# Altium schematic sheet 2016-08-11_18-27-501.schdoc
size 331 x 152 mm; SheetNumber: 1; SheetTotal: 1
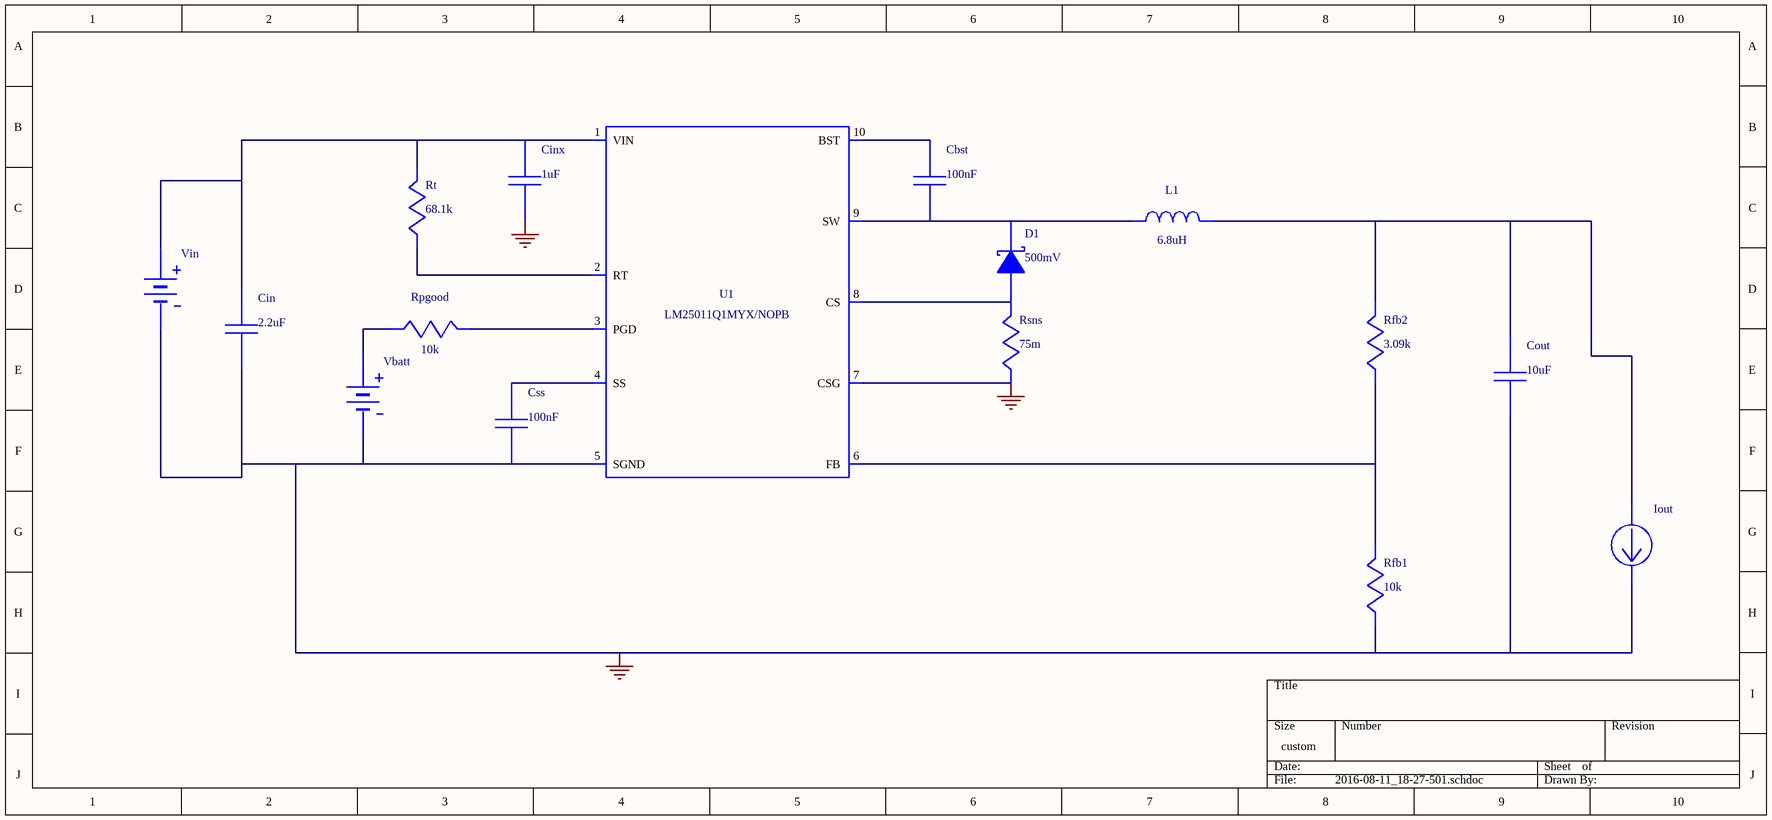
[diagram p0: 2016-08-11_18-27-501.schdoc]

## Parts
Cbst  value 100nF  (hidden comment: GRM21BR71E104KA01L)
Cin  value 2.2uF  (hidden comment: GRM31CR71H225KA88L)
Cinx  value 1uF  (hidden comment: GMK212B7105KG-T)
Cout  value 10uF  (hidden comment: GRM188R60J106ME47D)
Css  value 100nF  (hidden comment: GRM21BR71E104KA01L)
D1  value 500mV  (hidden comment: B240A-13-F)
Iout  WB_CURRENT_LOAD  (value not drawn)
L1  value 6.8uH  (hidden comment: SRN6045-6R8Y)
Rfb1  value 10k  (hidden comment: CRCW040210K0FKED)
Rfb2  value 3.09k  (hidden comment: CRCW04023K09FKED)
Rpgood  value 10k  (hidden comment: CRCW040210K0FKED)
Rsns  value 75m  (hidden comment: CSR1206FK75L0)
Rt  value 68.1k  (hidden comment: CRCW040268K1FKED)
U1  LM25011Q1MYX/NOPB
Vbatt  WB_PRIMITIVE_BATTERY  (value not drawn)
Vin  WB_BATTERY  (value not drawn)

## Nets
0: Cin.2 Cinx.2 Cout.2 Css.2 Iout.2(-) Rfb1.2 Rsns.2 U1.5(SGND) U1.7(CSG) U1.11(DAP) Vbatt.2(-) Vin.2(-)
NetCbst_1: Cbst.1 U1.10(BST)
NetCbst_2: Cbst.2 D1.1(K) L1.1 U1.9(SW)
NetCin_1: Cin.1 Cinx.1 Rt.1 U1.1(VIN) Vin.1(+)
NetCout_1: Cout.1 Iout.1(+) L1.2 Rfb2.1
NetCss_1: Css.1 U1.4(SS)
NetD1_2: D1.2(A) Rsns.1 U1.8(CS)
NetRfb1_1: Rfb1.1 Rfb2.2 U1.6(FB)
NetRpgood_1: Rpgood.1 U1.3(PGD)
NetRpgood_2: Rpgood.2 Vbatt.1(+)
NetRt_2: Rt.2 U1.2(RT)

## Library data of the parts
Cbst Css = GRM21BR71E104KA01L: GRM21BR71E104KA0; Manufacturer Name: MuRata
Cin = GRM31CR71H225KA88L: GRM31CR71H225KA8; Manufacturer Name: MuRata
Cinx = GMK212B7105KG-T: Manufacturer Name: Taiyo Yuden
Cout = GRM188R60J106ME47D: GRM188R60J106ME4; Manufacturer Name: MuRata
D1 = B240A-13-F: Manufacturer Name: Diodes Inc.
L1 = SRN6045-6R8Y: Manufacturer Name: Bourns
Rfb1 Rpgood = CRCW040210K0FKED: Manufacturer Name: Vishay-Dale
Rfb2 = CRCW04023K09FKED: Manufacturer Name: Vishay-Dale
Rsns = CSR1206FK75L0: Manufacturer Name: Stackpole Electronics Inc
Rt = CRCW040268K1FKED: Manufacturer Name: Vishay-Dale
U1 = LM25011Q1MYX/NOPB: LM25011Q1MYX/NOP; Manufacturer Name: Texas Instruments
Vbatt = WB_PRIMITIVE_BATTERY: WB_PRIMITIVE_BAT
